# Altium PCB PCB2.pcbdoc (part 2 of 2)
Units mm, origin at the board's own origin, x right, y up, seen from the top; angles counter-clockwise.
Board outline 189.74 x 136.02 mm, 2 copper layers (Top Layer, Bottom Layer); 111 components, 66 nets, 434 pads, 460 vias.
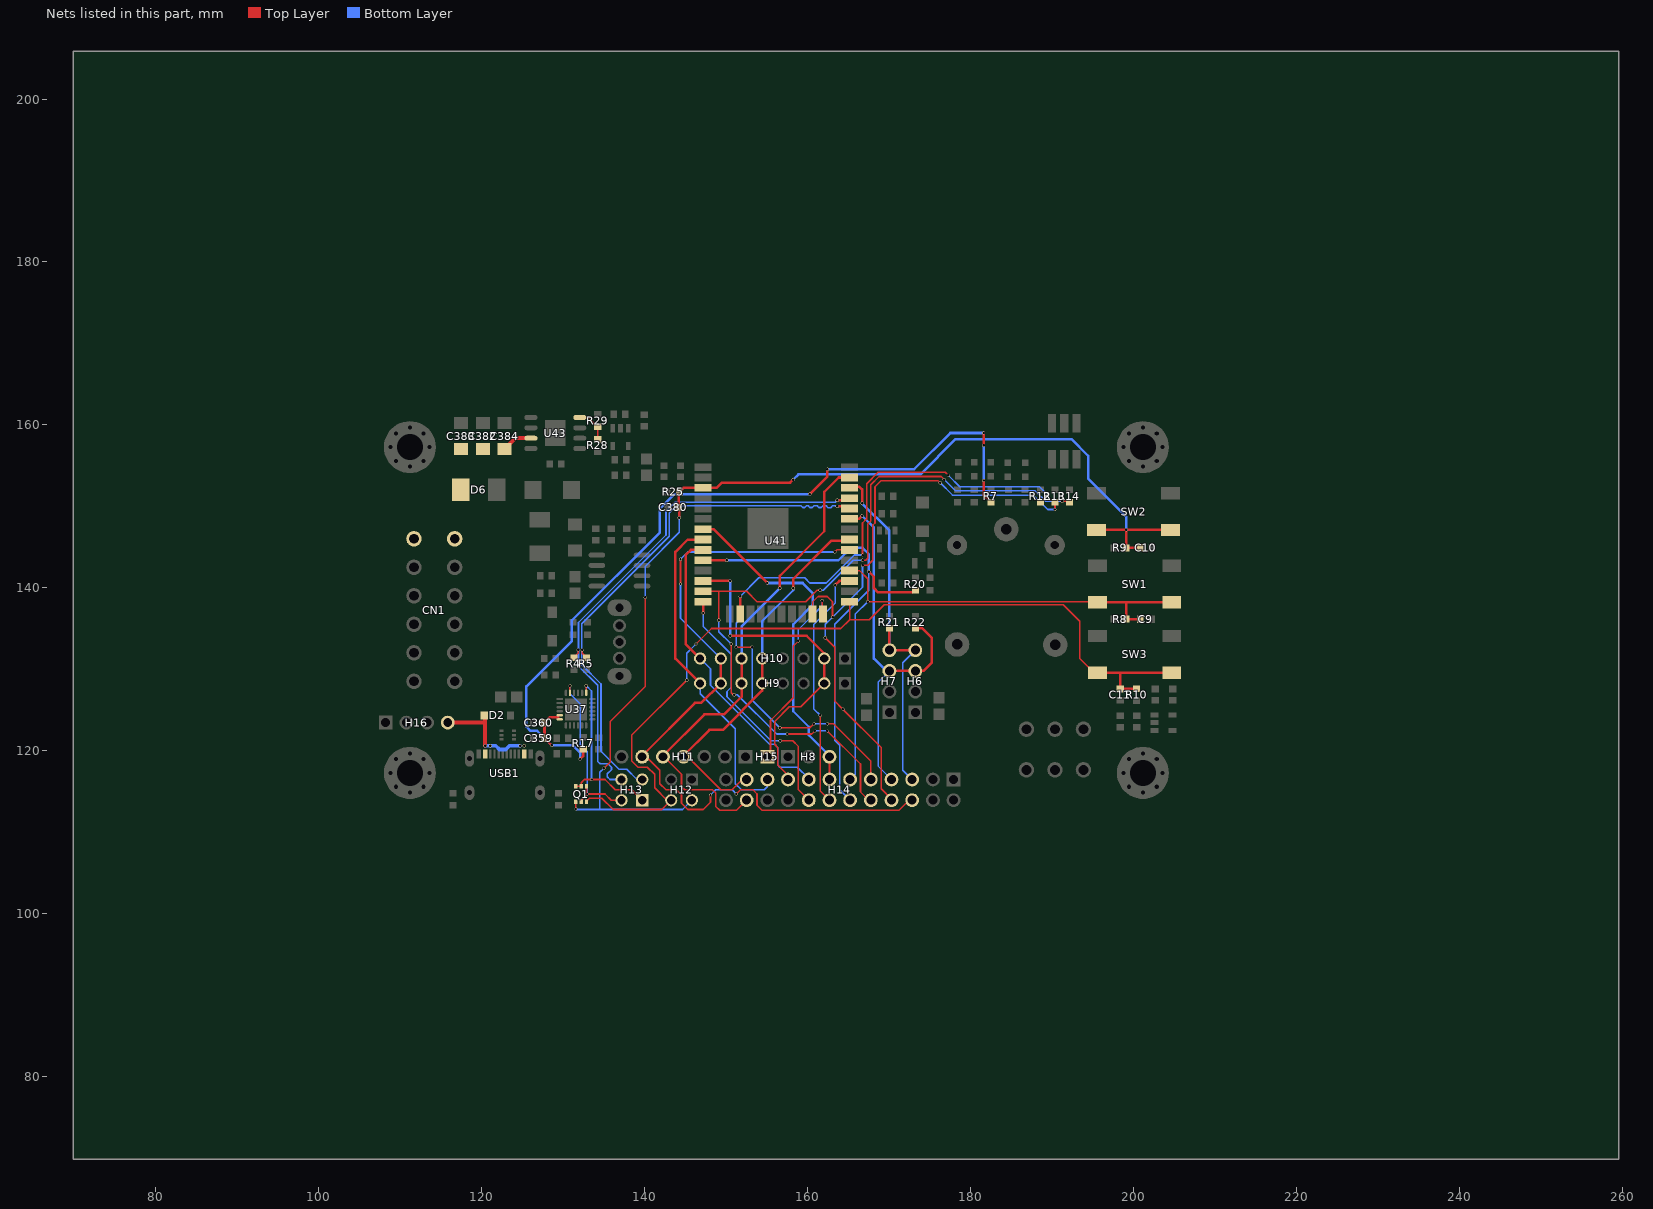
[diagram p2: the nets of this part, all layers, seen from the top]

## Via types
v1: diameter 0.4, hole 0.3, Top Layer to Bottom Layer, 460 vias

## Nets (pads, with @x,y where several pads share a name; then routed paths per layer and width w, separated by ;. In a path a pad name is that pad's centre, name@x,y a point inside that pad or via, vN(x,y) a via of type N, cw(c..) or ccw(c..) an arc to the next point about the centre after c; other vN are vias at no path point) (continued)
DTR: H13.2 Q1.1 Q1.5 U37.23 | length 21.9
  Top Layer w0.2: U37.23@130.822,127.095 v1(130.822,127.984) ; Q1.5@132.207,113.731 132.207,113.919 v1(132.969,114.681) ; Q1.1@132.857,115.631 132.857,114.681 v1(132.969,114.681) ; H13.2@137.16,113.919 135.89,113.919 135.128,114.681 v1(132.969,114.681)
  Bottom Layer w0.2: v1(130.822,127.984) 130.822,126.988 132.08,125.73 132.08,120.777 132.969,119.888 v1(132.969,114.681)
EN: C10.1 C380.1 H12.2 Q1.4 R9.1 R25.2 SW2.3 SW2.4 U41.3 | length 136.5
  Top Layer w0.2: v1(131.557,112.842) Q1.4@131.557,113.731 ; v1(135.001,117.856) 135.763,118.618 135.763,123.571 140.081,127.889 v1(140.081,138.811)
  Top Layer w0.312: v1(144.261,148.59) 144.261,149.809 C380.1@144.21,149.86 144.21,151.712 R25.2@144.263,151.765 144.769,152.271 U41.3@147.172,152.271 148.842,152.271 149.479,152.908 157.863,152.908 v1(158.242,153.287) ; SW2.3@195.475,147.102 v1(199.154,147.102) ; C10.1@200.849,144.907 R9.1@199.127,144.907 199.154,144.933 v1(199.154,147.102) ; SW2.4@204.575,147.102 v1(199.154,147.102)
  Bottom Layer w0.2: v1(131.557,112.842) 131.623,112.776 134.479,112.776 ; v1(135.001,117.856) 134.479,117.334 134.479,112.776 ; v1(140.081,138.811) 140.081,142.621 144.261,146.801 v1(144.261,148.59) ; H12.2@145.796,113.919 144.653,112.776 134.479,112.776
  Bottom Layer w0.312: v1(158.242,153.287) 158.879,153.924 173.863,153.924 178.181,158.242 192.405,158.242 194.437,156.21 194.437,153.416 199.136,148.717 v1@199.136,147.066
FB: R28.1 R29.1 U43.4 | length 4.2
  Top Layer w0.2: U43.4@132.032,160.909 133.096,160.909 134.23,159.775 R29.1@134.239,159.775 R28.1@134.239,158.233
GND: 
IO0: C11.1 H12.4 Q1.6 R10.1 SW3.3 SW3.4 U41.25 | length 109.9
  Top Layer w0.2: Q1.6@132.857,113.731 132.857,113.807 133.223,114.173 134.747,114.173 136.144,112.776 142.113,112.776 H12.4@143.256,113.919 142.748,113.919 141.224,115.443 141.224,117.094 140.335,117.983 139.192,117.983 138.43,118.745 138.43,121.92 v1(145.161,128.651) ; v1(146.304,133.096) 148.209,135.001 164.084,135.001 165.172,136.089 ; U41.25@165.172,138.301 165.172,136.089 ; SW3.3@195.602,129.576 195.163,129.576 193.421,131.318 193.421,135.89 191.389,137.922 169.418,137.922 167.585,136.089 165.172,136.089
  Top Layer w0.312: SW3.3@195.602,129.576 198.422,129.576 ; R10.1@200.406,127.626 198.427,127.626 C11.1@198.374,127.573 198.374,129.528 198.422,129.576 ; SW3.4@204.702,129.576 198.422,129.576
  Bottom Layer w0.2: v1(145.161,128.651) 145.161,131.953 v1(146.304,133.096)
IO2: H15.1 U41.24 | length 23.7
  Top Layer w0.2: H15.1@155.067,119.253 155.448,119.634 155.448,123.698 158.242,126.492 158.242,132.842 v1(158.877,133.477) ; v1(161.798,138.43) 161.798,136.87 U41.24@161.887,136.781
  Bottom Layer w0.2: v1(158.877,133.477) 158.877,134.874 161.798,137.795 v1(161.798,138.43)
IO12: H14.16 U41.14 | length 31.7
  Top Layer w0.2: v1(156.654,121.221) 158.178,121.221 158.877,120.523 158.877,115.189 H14.16@160.147,113.919
  Top Layer w0.312: U41.14@147.172,138.301 147.193,138.28 v1(147.193,136.906)
  Bottom Layer w0.2: v1(147.193,136.906) 147.193,135.255 150.622,131.826 150.622,127.762 150.114,127.254 150.114,126.619 155.511,121.221 v1(156.654,121.221)
IO16: H14.14 U41.27 | length 30.3
  Top Layer w0.2: v1(161.544,124.333) 161.544,115.062 H14.14@162.687,113.919
  Top Layer w0.312: v1(163.394,140.333) 163.902,140.841 U41.27@165.172,140.841
  Bottom Layer w0.2: v1(161.544,124.333) 160.782,125.095 160.782,135.509 163.394,138.121 v1(163.394,140.333)
IO35: H8.3 H14.13 U41.7 | length 42.4
  Top Layer w0.2: H14.13@162.687,116.459 H8.3@162.687,119.38
  Top Layer w0.312: U41.7@147.172,147.191 148.465,147.191 v1(155.067,140.589)
  Bottom Layer w0.312: v1(155.067,140.589) 159.385,140.589 160.655,139.319 160.655,137.922 158.242,135.509 158.242,124.841 160.147,122.936 160.147,121.92 H8.3@162.687,119.38
LED_B: H14.10 R14.1 U41.13 | length 96.3
  Top Layer w0.2: U41.13@147.172,139.571 149.098,139.571 ; v1(149.098,136.017) 149.098,139.571 ; v1(150.622,133.096) 150.622,127.127 150.876,126.873 v1(151.003,126.873) ; v1(157.48,122.047) 160.528,122.047 v1(160.909,122.428) ; v1(161.544,139.698) 161.161,139.698 159.766,138.303 153.797,138.303 152.529,139.571 149.098,139.571 ; v1(162.433,122.428) 166.497,118.364 166.497,114.935 167.513,113.919 H14.10@167.767,113.919 ; v1(166.751,143.383) 167.132,143.383 167.386,143.637 167.386,147.828 167.767,148.209 167.767,152.654 168.783,153.67 176.403,153.67 v1(176.784,153.289) ; v1(191.262,150.631) 192.024,150.631 R14.1@192.151,150.504
  Bottom Layer w0.2: v1(149.098,136.017) 149.098,134.62 v1(150.622,133.096) ; v1(151.003,126.873) 151.384,126.873 156.21,122.047 v1(157.48,122.047) ; v1(160.909,122.428) v1(162.433,122.428) ; v1(161.544,139.698) 161.923,139.698 165.608,143.383 v1(166.751,143.383) ; v1(176.784,153.289) 178.181,151.892 187.96,151.892 189.23,150.622 v1@191.262,150.622
LED_G: H14.8 R13.1 U41.23 | length 75.9
  Top Layer w0.2: U41.23@160.617,136.781 160.617,138.265 161.29,138.938 162.433,138.938 163.068,138.303 v1(163.068,136.398) ; v1(162.179,133.858) 163.322,132.715 163.322,126.111 v1(164.338,125.095) 169.037,120.396 169.037,115.316 170.307,114.046 H14.8@170.307,113.919 ; v1(166.751,142.748) 167.386,142.748 168.021,143.383 168.021,147.701 168.275,147.955 168.275,152.4 169.037,153.162 176.022,153.162 v1(176.276,152.908) ; v1(190.373,149.615) R13.1@190.373,150.504
  Bottom Layer w0.2: v1(162.179,133.858) 162.179,135.509 v1(163.068,136.398) 166.751,140.081 v1(166.751,142.748) ; v1(176.276,152.908) 177.8,151.384 187.706,151.384 189.475,149.615 v1(190.373,149.615)
LED_R: H14.9 R12.1 U41.16 | length 89.2
  Top Layer w0.2: v1(151.257,132.715) v1(153.191,132.715) ; v1(156.591,122.809) 160.274,122.809 v1(160.782,123.317) ; v1(162.433,123.317) 163.195,123.317 167.767,118.745 H14.9@167.767,116.459 ; v1(166.751,144.018) 166.751,147.955 167.259,148.463 167.259,152.781 168.656,154.178 176.911,154.178 v1(177.292,153.797) ; R12.1@188.595,150.504 v1(189.484,151.393)
  Top Layer w0.312: U41.16@151.727,136.781 v1(151.727,138.94)
  Bottom Layer w0.2: v1(151.257,132.715) 151.257,135.636 151.727,136.106 v1(151.727,138.94) 154.011,141.224 159.639,141.224 160.274,140.589 162.306,140.589 165.735,144.018 v1(166.751,144.018) ; v1(153.191,132.715) 153.191,126.209 v1(156.591,122.809) ; v1(160.782,123.317) v1(162.433,123.317) ; v1(177.292,153.797) 178.689,152.4 188.477,152.4 v1(189.484,151.393)
MISO: H9.5 H10.5 H11.4 H14.21 U41.31 | length 46.6
  Top Layer w0.2: H11.4@144.78,119.38 145.161,119.38 149.352,115.189 150.726,115.189 151.996,116.459 H14.21@152.527,116.459
  Top Layer w0.312: H11.4@144.78,119.38 147.955,122.555 149.596,122.555 154.432,127.391 H9.5@154.432,128.27 H10.5@154.432,131.318 ; v1(158.242,139.954) 158.242,141.097 162.941,145.796 165.047,145.796 U41.31@165.172,145.921
  Bottom Layer w0.312: H10.5@154.432,131.953 154.432,135.89 158.242,139.7 v1(158.242,139.954)
MOSI: H9.6 H10.6 H11.5 H14.22 U41.37 | length 60.7
  Top Layer w0.2: H11.5@142.24,119.38 144.526,117.094 144.526,115.57 144.907,115.189 148.336,115.189 148.717,114.808 148.717,113.157 149.206,112.668 151.276,112.668 H14.22@152.527,113.919
  Top Layer w0.312: H11.5@142.24,119.38 147.32,124.46 149.733,124.46 151.892,126.619 H9.6@151.892,128.27 H10.6@151.892,131.318 ; v1(156.591,139.954) 156.591,141.478 162.052,146.939 162.052,151.765 163.83,153.543 165.17,153.543 U41.37@165.172,153.541
  Bottom Layer w0.312: H10.6@151.892,131.953 151.892,135.255 v1(156.591,139.954)
RELAY: H14.12 R20.1 U41.10 | length 61.7
  Top Layer w0.312: U41.10@147.172,143.381 v1(150.093,143.381) ; v1(167.515,141.986) 168.148,141.353 168.148,139.954 168.656,139.446 172.847,139.446 173.11,139.709 R20.1@173.228,139.709
  Bottom Layer w0.2: H14.12@165.227,113.919 163.957,115.189 163.957,120.65 163.322,121.285 163.322,135.509 167.515,139.702 v1(167.515,141.986)
  Bottom Layer w0.312: v1(150.093,143.381) 163.785,143.381 165.311,144.907 166.751,144.907 167.515,144.143 v1(167.515,141.986)
RFID0_SS: H9.8 H14.19 U41.8 | length 40.6
  Top Layer w0.312: H9.8@146.431,128.651 143.764,131.318 143.764,144.399 145.286,145.921 U41.8@147.172,145.921 ; H9.8@146.558,128.778 H9.8@146.812,128.778
  Bottom Layer w0.2: H9.8@146.812,128.27 146.812,127 151.13,122.682 151.13,115.951 151.892,115.189 154.686,115.189 155.067,115.57 H14.19@155.067,116.459
RFID1_SS: H10.8 H14.15 U41.9 | length 37.9
  Top Layer w0.312: H10.8@146.812,131.318 145.034,133.096 145.034,144.018 145.667,144.651 U41.9@147.172,144.651
  Bottom Layer w0.2: H10.8@146.812,131.318 148.082,130.048 148.082,128.016 155.321,120.777 155.956,120.777 156.337,120.396 156.337,118.237 156.591,117.983 158.75,117.983 160.147,116.586 H14.15@160.147,116.459
RFID_RST: H9.2 H10.2 H14.17 U41.12 | length 41.4
  Top Layer w0.2: H14.17@157.607,116.459 157.607,116.967 156.337,118.237 156.337,120.396 155.956,120.777 155.956,123.571 157.761,125.376 159.158,125.376 H9.2@162.052,128.27
  Top Layer w0.312: U41.12@147.172,140.841 v1(150.497,140.841) ; v1(150.495,134.112) 159.893,134.112 H10.2@162.052,131.953 ; H9.2@162.052,128.27 H10.2@162.052,131.318
  Bottom Layer w0.312: v1(150.495,134.112) 150.497,134.114 v1(150.497,140.841)
RTS: H13.1 Q1.2 Q1.3 U37.19 | length 22.5
  Top Layer w0.2: Q1.3@131.557,115.631 Q1.2@132.207,115.631 132.207,116.078 132.588,116.459 v1(133.477,116.459) 135.128,116.459 136.398,115.189 138.43,115.189 H13.1@139.7,113.919 ; U37.19@132.822,127.095 v1(132.822,127.984)
  Bottom Layer w0.2: v1(132.822,127.984) 133.477,127.329 v1(133.477,116.459)
RX: H13.4 R4.2 U41.35 | length 65.8
  Top Layer w0.2: R4.2@131.318,131.436 131.826,131.944 v1(131.826,132.367)
  Top Layer w0.312: v1(163.648,150.747) 164.706,150.747 164.96,151.001 U41.35@165.172,151.001
  Bottom Layer w0.2: H13.4@137.16,116.459 135.737,116.459 135.409,116.787 135.409,117.159 135.92,117.67 135.92,117.953 135.493,118.38 134.534,118.38 134.239,118.675 134.239,128.016 131.88,130.375 131.88,132.313 v1(131.826,132.367) 131.88,132.421 131.88,135.748 142.621,146.489 142.621,149.352 143.764,150.495 163.396,150.495 v1(163.648,150.747)
SCK: H9.7 H10.7 H11.6 H14.6 U41.30 | length 93.6
  Top Layer w0.2: H11.6@139.7,119.253 140.208,119.253 141.859,117.602 141.859,115.951 142.621,115.189 143.891,115.189 144.526,114.554 144.526,113.538 145.288,112.776 147.193,112.776 148.082,113.665 v1(148.082,114.554) ; v1(144.399,140.462) v1(144.399,143.51) ; v1(151.257,114.681) 151.765,115.189 153.289,115.189 153.797,114.681 153.797,113.284 154.413,112.668 171.215,112.668 172.466,113.919 H14.6@172.847,113.919 ; v1(163.322,144.399) 163.574,144.651 U41.30@165.172,144.651
  Top Layer w0.312: H11.6@139.7,119.38 146.177,125.857 146.939,125.857 H9.7@149.352,128.27 H10.7@149.352,131.318
  Bottom Layer w0.2: v1(144.399,140.462) 144.399,136.271 H10.7@149.352,131.318 ; v1(144.399,143.51) 145.288,144.399 v1(163.322,144.399) ; v1(148.082,114.554) 148.717,115.189 150.749,115.189 v1(151.257,114.681)
SCL: H6.4 H7.4 H14.5 R21.2 U41.36 | length 45.7
  Top Layer w0.312: U41.36@165.172,152.271 165.301,152.4 166.37,152.4 166.696,152.074 v1(166.696,150.366) ; R21.2@170.053,135.01 H7.4@170.053,132.334 H6.4@173.228,132.334
  Bottom Layer w0.2: H14.5@172.847,116.459 171.704,117.602 171.704,130.81 H6.4@173.228,132.334
  Bottom Layer w0.312: v1(166.696,150.366) 170.053,147.009 H7.4@170.053,132.334
SDA: H6.3 H7.3 H14.7 R22.2 U41.33 | length 48.1
  Top Layer w0.312: U41.33@165.172,148.461 166.315,148.461 v1(166.696,148.842) ; H7.3@170.053,129.794 H6.3@173.228,129.794 174.244,129.794 175.26,130.81 175.26,133.858 174.108,135.01 R22.2@173.228,135.01
  Bottom Layer w0.2: H7.3@170.053,129.794 168.656,128.397 168.656,118.11 H14.7@170.307,116.459
  Bottom Layer w0.312: v1(166.696,148.842) 168.148,147.39 168.148,131.318 169.672,129.794 H7.3@170.053,129.794
SW: C9.1 H14.11 R8.1 SW1.3 SW1.4 U41.28 | length 69.3
  Top Layer w0.2: U41.28@165.172,142.111 166.372,142.111 167.386,141.097 v1(167.386,138.303) 195.511,138.303 SW1.3@195.602,138.212
  Top Layer w0.312: SW1.3@195.602,138.212 199.111,138.212 ; C9.1@200.849,136.144 R8.1@199.127,136.144 199.127,138.196 199.111,138.212 ; SW1.4@204.702,138.212 199.111,138.212
  Bottom Layer w0.2: H14.11@165.227,116.459 165.862,117.094 165.862,136.779 v1(167.386,138.303)
TX: H13.3 R5.2 U41.34 | length 65.8
  Top Layer w0.2: v1(132.334,132.367) 132.334,131.944 R5.2@132.842,131.436
  Top Layer w0.312: v1(163.648,149.985) 164.706,149.985 164.96,149.731 U41.34@165.172,149.731
  Bottom Layer w0.2: H13.3@139.7,116.459 139.065,116.459 137.795,117.729 136.837,117.729 134.639,119.927 134.639,128.182 132.28,130.541 132.28,132.313 v1(132.334,132.367) 132.28,132.421 132.28,135.582 143.021,146.323 143.021,149.186 143.93,150.095 159.169,150.095 159.413,149.852 159.672,149.852 159.88,150.06 160.073,150.06 160.273,149.86 160.578,149.86 160.778,150.06 161.172,150.06 161.372,149.86 161.69,149.86 161.902,150.072 162.281,150.072 162.512,149.841 162.85,149.841 163.104,150.095 163.538,150.095 v1(163.648,149.985)
USB5V: D2.1 H16.4 USB1.2 USB1.11 | length 13
  Top Layer w0.5: H16.4@115.824,123.444 120.387,123.444 120.409,123.466 ; D2.1@120.31,124.333 120.409,124.234 120.409,123.466 ; v1(120.409,120.612) 120.409,123.466
  Bottom Layer w0.44: v1(120.409,120.612) v1(121.044,120.612) 121.704,120.612 122.174,120.142 122.936,120.142 123.406,120.612 v1(124.701,120.612)
  other v1: 125.209,120.612
VCC: C382.2 C383.2 C384.2 CN1.1 D6.2 U43.7 | length 3.8
  Top Layer w0.5: C384.2@122.809,157.03 124.148,158.369 U43.7@126.032,158.369
VDD: C359.2 C360.2 R7.1 R17.1 U37.5 U37.6 | length 101.8
  Top Layer w0.312: v1(128.589,120.65) C359.2@127.7,121.539 C360.2@127.7,123.444 128.335,124.079 129.413,124.079 ; v1(132.08,118.966) 132.461,119.347 R17.1@132.461,120.151 ; v1(160.274,151.511) 162.433,153.67 v1(162.433,154.559) ; v1(181.61,153.171) 181.61,151.393 R7.1@182.499,150.504 ; v1(181.61,157.48) v1(181.61,159.004)
  Bottom Layer w0.312: v1(132.08,118.966) 132.08,119.761 131.191,120.65 v1(128.589,120.65) 126.811,122.428 125.984,122.428 125.476,122.936 125.476,127.889 131.064,133.477 131.064,136.017 141.859,146.812 141.859,149.733 143.637,151.511 v1(160.274,151.511) ; v1(162.433,154.559) 173.101,154.559 177.546,159.004 v1(181.61,159.004) ; v1(181.61,153.171) v1(181.61,157.48)
pads on no net: C1.2 C2.2 C3.2 C6.1 C9.2 C10.2 C11.2 C351.1 C352.1 C353.1 C354.1 C355.1 C356.1 C357.1 C358.1 C359.1 C360.1 C361.1 C362.1 C363.2 C364.2 C369.1 C370.1 C371.1 C372.1 C373.1 C374.1 C375.1 C376.1 C377.2 C378.2 C379.2 C380.2 C382.1 C383.1 C384.1 C385.1 C386.1 C387.1 C388.1 CN1.2 D1.2 D5.2 D6.1 H1.1 H2.1 H3.1 H4.1 H6.1 H7.1 H8.1 H9.3 H9.4 H10.3 H10.4 H11.2 H12.3 H14.3 H14.4 H16.1 LED白.1 LED红.2 LED绿.1 LED蓝.2 Q2.2 R1.2 R2.2 R15.2 R19.2 R29.2 SW1.1 SW1.2 SW2.1 SW2.2 SW3.1 SW3.2 U31.2 U31.4 U34.2 U36.3 U36.4 U36.5 U37.1 U37.2 U37.10 U37.11 U37.12 U37.13 U37.14 U37.15 U37.17 U37.18 U37.22 U37.24 U37.25 U40.2 U40.4 U41.1 U41.4 U41.5 U41.15 U41.17 U41.18 U41.19 U41.20 U41.21 U41.22 U41.32 U41.38 U41.39 U42.2 U42.4 U43.2 U43.3 U43.5 U43.6 U43.9 USB1.1 USB1.3 USB1.9 USB1.12 USB1.13 USB1.14
copper on no net: | length 8.8
  Top Layer w0.2: v1(122.936,123.19) 124.079,123.19 124.46,123.571 124.46,124.714 126.111,126.365 128.29,126.365 v1(128.81,125.845) 129.572,125.845
  other v1: 125.603,113.157 169.037,113.157 156.337,113.284 133.731,113.538 141.351,113.792 138.43,113.919 122.047,114.681 160.782,115.189 167.138,115.189 168.408,115.189 133.731,115.316 135.161,115.367 138.43,115.881 147.066,116.078 123.388,116.134 136.017,116.967 116.078,117.094 129.921,117.094 149.097,117.475 151.638,117.475 147.828,117.729 155.956,117.729 131.572,117.856 145.542,117.856 160.782,117.856 162.052,117.856 167.132,118.364 169.926,118.745 178.306,118.745 164.846,118.872 134.874,118.999 107.569,120.396 163.12,120.63 174.752,120.65 153.67,120.777 204.47,120.777 122.428,120.904 159.893,120.904 114.681,121.031 142.621,121.031 119.126,121.158 145.288,121.158 162.306,121.158 167.005,121.158 136.398,121.793 121.031,121.92 170.942,121.92 140.589,122.047 172.974,122.047 112.014,122.174 150.495,122.301 178.181,122.428 118.364,122.682 146.812,122.682 154.813,122.682 164.846,122.809 129.295,122.878 141.478,122.936 144.706,123.13 157.226,123.444 203.791,123.507 139.202,123.825 142.299,123.831 130.556,124.067 132.588,124.067 160.655,124.079 114.554,124.206 127,124.281 162.596,124.289 121.92,124.333 137.922,124.587 152.908,124.587 135.509,124.841 140.462,124.968 131.572,125.083 146.685,125.095 194.691,125.095 118.11,125.603 144.526,125.603 113.665,125.73 130.556,126.099 132.588,126.099 119.38,126.238 156.718,126.492 161.798,126.492 162.596,126.492 159.258,126.746 135.89,126.873 140.335,127.127 128.651,127.254 137.668,127.254 195.961,127.254 143.129,127.762 194.183,128.016 129.921,128.143 125.603,129.286 141.478,129.413 175.768,129.54 146.939,129.667 122.428,129.794 149.987,129.794 151.226,129.794 152.542,129.794 153.797,129.794 155.067,129.794 157.099,129.794 159.512,129.794 161.29,129.921 167.005,129.921 114.3,130.048 130.302,130.048 134.606,130.063 199.263,130.556 108.585,130.683 126.365,130.683 174.498,131.175 134.606,131.624 195.081,131.826 120.65,131.953 167.005,131.99 204.216,132.08 144.526,132.207 198.755,132.207 141.859,132.588 162.306,132.842 159.639,132.969 155.035,133.096 157.099,133.096 164.465,133.096 174.498,133.322 152.781,133.477 114.046,133.731 115.65,133.731 130.048,133.731 145.669,133.731 168.91,133.985 171.678,133.985 161.417,134.112 125.603,134.177 135.001,134.366 164.846,134.366 167.132,135.001 143.129,135.128 123.698,135.382 141.859,135.484 134.239,135.763 204.47,135.763 175.133,136.017 169.037,136.652 126.492,136.779 146.177,136.779 179.578,136.779 188.849,136.779 167.259,136.906 148.209,137.033 119.256,137.208 114.554,137.414 143.129,138.227 152.529,138.383 154.178,138.811 129.921,138.938 136.906,139.231 125.349,139.319 176.945,139.7 179.324,139.7 199.136,139.954 141.859,140.021 129.921,140.28 204.702,140.462 151.511,140.589 143.129,140.908 188.341,140.97 192.676,140.97 108.795,141.097 114.574,141.097 119.507,141.097 162.179,141.224 169.037,141.732 177.292,142.113 200.152,142.22 171.958,142.748 156.122,142.823 151.003,142.875 178.816,143.002 129.54,143.256 141.859,143.255 143.129,143.467 135.89,143.758 168.91,143.764 124.527,143.997 152.996,145.109 155.155,145.109 157.314,145.109 149.098,145.161 161.163,145.161 193.548,145.161 121.92,145.288 145.542,145.288 108.331,145.415 129.168,145.492 172.339,145.551 144.145,145.796 145.288,146.812 163.195,146.913 124.968,146.939 160.02,147.066 152.996,147.268 155.155,147.268 157.314,147.268 188.341,147.447 129.727,147.601 177.927,147.701 143.637,147.828 169.799,148.046 159.258,148.336 200.406,148.336 137.668,148.59 149.86,148.59 163.195,148.59 180.782,148.593 122.555,148.844 135.001,148.971 176.911,148.971 193.548,148.998 108.839,149.225 145.542,149.352 203.79,149.352 152.996,149.427 155.155,149.427 157.314,149.427 172.339,149.479 112.649,149.733 132.08,149.733 169.037,150.108 169.799,150.108 199.238,150.647 136.906,150.876 141.986,151.003 149.524,151.003 157.353,151.003 161.29,151.257 163.322,151.511 134.239,151.59 176.276,151.638 113.919,152.019 124.333,152.138 173.99,152.146 201.425,152.524 193.548,152.78 108.458,152.908 148.971,153.289 128.143,153.67 196.342,153.67 145.542,154.305 115.316,154.432 149.352,154.559 153.072,154.559 155.702,154.559 159.081,154.559 177.722,154.546 188.849,154.566 120.65,154.686 133.096,154.813 135.128,155.067 124.333,155.575 168.402,156.464 128.044,156.504 180.848,156.591 130.683,156.718 137.096,157.284 188.849,157.353 180.086,157.48 128.143,157.734 129.921,157.734 194.437,157.861 171.45,158.242 118.497,158.623 121.302,158.623 129.032,159.004 133.223,159.131 142.186,159.229 138.868,159.448 170.307,159.639 144.272,159.766 128.143,160.274 129.921,160.274 196.342,160.274 143.002,160.782 114.046,160.909 175.766,161.036 181.362,161.036 184.785,161.036 129.413,161.417 188.722,161.417 124.587,161.544

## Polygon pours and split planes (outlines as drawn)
USB5V on Top Layer (solid, remove dead copper): 120.09,119.026 120.704,119.026 120.704,121.02 120.09,121.02
USB5V on Bottom Layer (solid, remove dead copper, pour order 64): 120.015,120.269 121.412,120.269 121.412,121.031 120.015,121.031
USB5V on Top Layer (solid, remove dead copper, pour order 2): 120.09,120.339 121.324,120.339 121.324,121.031 120.09,121.031
+5V on Bottom Layer (solid, remove dead copper, pour order 66): 127.725,134.338 129.527,134.338 129.527,135.514 127.725,135.514
USB5V on Top Layer (solid, remove dead copper, pour order 4): 124.405,120.343 125.511,120.343 125.511,120.933 124.405,120.933
$1N9535 on Bottom Layer (solid, remove dead copper, pour order 68): 188.595,116.078 192.024,116.078 192.024,126.873 188.595,126.873
VDD on Top Layer (solid, remove dead copper, pour order 6): 129.032,123.571 130.048,123.571 130.048,124.587 129.032,124.587
$1N9535 on Bottom Layer (solid, remove dead copper, pour order 70): 182.245,126.131 186.69,126.131 186.69,149.479 182.245,149.479
$1N9535 on Bottom Layer (solid, remove dead copper, pour order 72): 182.245,125.73 192.024,125.73 192.024,130.048 182.245,130.048
+5V on Top Layer (solid, remove dead copper, pour order 8): 130.048,122.555 131.064,122.555 131.064,123.571 130.048,123.571
VCC on Top Layer (solid, remove dead copper, pour order 10): 110.109,144.653 118.491,144.653 118.491,147.574 110.109,147.574
3V3 on Bottom Layer (solid, remove dead copper, pour order 74): 200.877,125.483 202.292,125.483 202.292,126.873 200.877,126.873
VCC on Top Layer (solid, remove dead copper, pour order 12): 116.332,146.812 118.491,146.812 118.491,153.416 116.332,153.416
$1N9531 on Bottom Layer (solid, remove dead copper, pour order 76): 184.785,116.078 188.214,116.078 188.214,124.206 184.785,124.206
$1N9540 on Bottom Layer (solid, remove dead copper, pour order 78): 192.405,116.078 195.326,116.078 195.326,124.206 192.405,124.206
VCC on Top Layer (solid, remove dead copper, pour order 14): 116.332,153.416 118.453,153.416 118.453,157.773 116.332,157.773
3.3_SENSOR on Bottom Layer (solid, remove dead copper, pour order 80): 170.97,139.97 171.958,139.97 171.958,141.226 170.97,141.226
VCC on Top Layer (solid, remove dead copper, pour order 16): 116.309,156.059 123.641,156.059 123.641,157.773 116.309,157.773
+5V on Top Layer (solid, remove dead copper, pour order 18): 127.762,133.803 129.493,133.803 129.493,135.509 127.762,135.509
3.3_SENSOR on Bottom Layer (solid, remove dead copper, pour order 82): 171.196,136.017 172.466,136.017 172.466,137.033 171.196,137.033
+5V on Bottom Layer (solid, remove dead copper, pour order 84): 196.977,122.047 197.866,122.047 197.866,124.079 196.977,124.079
3.3_SENSOR on Top Layer (solid, remove dead copper, pour order 20): 168.084,125.666 168.084,127.825 166.56,127.825 166.56,125.666
3V3 on Top Layer (solid, remove dead copper, pour order 22): 135.423,145.067 137.011,145.067 137.011,146.558 135.423,146.558
+5V on Bottom Layer (solid, remove dead copper, pour order 86): 124.587,121.539 125.755,121.539 125.755,122.682 124.587,122.682
$1N9540 on Top Layer (solid, remove dead copper, pour order 24): 181.356,112.195 195.23,112.195 195.23,115.697 181.356,115.697
+5V on Bottom Layer (solid, remove dead copper, pour order 88): 138.049,144.526 139.192,144.526 139.192,145.669 138.049,145.669
$1N9540 on Top Layer (solid, remove dead copper, pour order 26): 176.403,130.302 183.388,130.302 183.388,135.636 176.403,135.636
$1N9540 on Top Layer (solid, remove dead copper, pour order 28): 179.959,110.149 184.404,110.149 184.404,135.636 179.959,135.636
3V3 on Bottom Layer (solid, remove dead copper, pour order 90): 136.105,145.034 137.287,145.034 137.287,146.558 136.105,146.558
$1N9540 on Top Layer (solid, remove dead copper, pour order 30): 192.405,115.235 195.23,115.235 195.23,124.206 192.405,124.206
3V3 on Bottom Layer (solid, remove dead copper, pour order 92): 139.065,157.226 139.954,157.226 139.954,158.75 139.065,158.75
$1N9535 on Top Layer (solid, remove dead copper, pour order 32): 188.595,116.078 192.024,116.078 192.024,124.206 188.595,124.206
3V3 on Bottom Layer (solid, remove dead copper, pour order 94): 142.24,157.226 143.002,157.226 143.002,158.623 142.24,158.623
$1N9531 on Top Layer (solid, remove dead copper, pour order 34): 184.785,116.078 188.214,116.078 188.214,124.714 184.785,124.714
3V3 on Bottom Layer (solid, remove dead copper, pour order 96): 186.944,159.512 187.96,159.512 187.96,161.163 186.944,161.163
3V3 on Bottom Layer (solid, remove dead copper, pour order 98): 193.802,159.778 194.552,159.778 194.552,161.163 193.802,161.163
$1N9531 on Top Layer (solid, remove dead copper, pour order 36): 184.785,123.698 188.214,123.698 188.214,135.636 184.785,135.636
$1N9531 on Top Layer (solid, remove dead copper, pour order 38): 184.785,130.683 192.278,130.683 192.278,135.636 184.785,135.636
3V3 on Top Layer (solid, remove dead copper, pour order 40): 200.877,125.483 202.292,125.483 202.292,126.873 200.877,126.873
3.3_SENSOR on Top Layer (solid, remove dead copper, pour order 42): 170.053,139.954 171.958,139.954 171.958,141.226 170.053,141.226
3.3_SENSOR on Top Layer (solid, remove dead copper, pour order 44): 171.196,136.017 172.466,136.017 172.466,137.033 171.196,137.033
3V3 on Top Layer (solid, remove dead copper, pour order 46): 139.065,157.226 139.954,157.226 139.954,158.75 139.065,158.75
3V3 on Top Layer (solid, remove dead copper, pour order 48): 142.24,157.226 143.002,157.226 143.002,158.623 142.24,158.623
3V3 on Top Layer (solid, remove dead copper, pour order 50): 186.944,159.512 187.96,159.512 187.96,161.163 186.944,161.163
3V3 on Top Layer (solid, remove dead copper, pour order 52): 193.802,159.778 194.552,159.778 194.552,161.163 193.802,161.163
+5V on Bottom Layer (solid, remove dead copper, pour order 100): 171.704,151.511 173.101,151.511 173.101,152.908 171.704,152.908
+5V on Top Layer (solid, remove dead copper, pour order 54): 171.704,151.003 173.101,151.003 173.101,152.908 171.704,152.908
USB5V on Top Layer (solid, remove dead copper, pour order 56): 119.761,123.19 120.777,123.19 120.777,124.841 119.761,124.841
USB5V on Top Layer (solid, remove dead copper, pour order 58): 124.405,120.269 125.603,120.269 125.603,120.933 124.405,120.933
USB5V on Top Layer (solid, remove dead copper, pour order 60): 124.909,119.025 125.511,119.025 125.511,120.933 124.909,120.933
no net on Top Layer (solid, remove dead copper, pour order 62): 92.964,95.885 229.235,95.885 229.235,179.324 92.964,179.324
no net on Bottom Layer (solid, remove dead copper, pour order 102): 76.2,76.2 253.238,76.2 253.238,199.517 76.2,199.517

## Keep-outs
Board Outline Layer:
  lines w0.254: 106.172,116.268 ccw(c110.172,116.268) 110.172,112.268 202.172,112.268 ccw(c202.172,116.268) 206.172,116.268 206.172,158.268 ccw(c202.172,158.268) 202.172,162.268 110.172,162.268 ccw(c110.172,158.268) 106.172,158.268 106.172,116.268
Multi-Layer:
  region: 144.907,155.746 167.856,155.746 167.856,163.449 144.907,163.449

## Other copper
Top Layer:
  drawing of 446 lines, arcs and shapes, not listed
Bottom Layer:
  drawing of 159 lines, arcs and shapes, not listed

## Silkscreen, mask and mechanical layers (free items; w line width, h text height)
Top Silkscreen Layer:
  drawing of 195 lines, arcs and shapes, not listed
  text "RELA Y\N" at 179.07,156.337 h1.1 r90
  text "POWER" at 181.229,156.337 h1.5 r90
  text "USB" at 183.261,156.337 h1.5 r90
  text "SENSOR" at 185.293,156.21 h1.5 r90
  text "5V>3V3" at 187.452,156.21 h1.5 r90
  text "RGBLED" at 188.849,152.908 h1.5
  text "EN" at 196.215,148.59 h1.5 r90
  text "EN" at 205.359,148.59 h1.5 r90
  text "12V" at 121.158,145.161 h1.5
  text "GND" at 121.285,141.732 h1.5
  text "SW" at 196.342,139.573 h1.5 r90
  text "SW" at 205.613,139.573 h1.5 r90
  text "CAN_H" at 121.158,138.557 h1.5
  text "CAN_L" at 121.158,134.747 h1.5
  text "RFID" at 160.782,133.985 h1
  text "ON" at 139.7,133.731 h1.5
  text "SCL" at 175.006,133.35 h1 r270
  text "SCK" at 148.336,132.969 h1
  text "MOSI" at 150.876,132.969 h1
  text "MISO" at 153.67,132.969 h1
  text "GND" at 158.242,132.969 h1
  text "3V3" at 163.576,132.969 h1
  text "RST" at 160.909,132.842 h1
  text "SCL" at 168.275,131.572 h1 r90
  text "CAN_H" at 121.285,131.318 h1.5
  text "OFF" at 139.7,131.191 h1.5
  text "RFID1" at 142.621,130.81 h1
  text "IO0" at 196.342,130.81 h1.5 r90
  text "IO0" at 205.486,130.81 h1.5 r90
  text "SDA" at 175.006,130.556 h1 r270
  text "SDA" at 168.275,128.778 h1 r90
  text "CAN_L" at 121.285,127.889 h1.5
  text "RFID0" at 142.494,127.762 h1
  text "3V3" at 177.419,125.984 h1
  text "IO2" at 154.559,125.73 h1
  text "GND" at 156.718,125.73 h1
  text "SENSOR" at 159.131,125.73 h1
  text "3V3" at 164.211,125.603 h1
  text "CAN" at 146.939,125.349 h1
  text "SENSOR" at 149.987,125.349 h1
  text "CAN" at 135.89,125.222 h1
  text "3V3" at 159.258,124.714 h1
  text "RF" at 154.686,124.333 h1
  text "RF" at 157.099,124.333 h1
  text "_INT" at 135.636,124.206 h1
  text "MISO" at 144.018,124.079 h1
  text "_CS" at 146.812,124.079 h1
  text "3V3" at 151.892,124.079 h1
  text "SCK" at 138.557,123.952 h1
  text "MOSI" at 141.097,123.952 h1
  text "GND" at 149.479,123.952 h1
  text "IO35" at 161.671,123.825 h1
  text "GND" at 177.419,123.825 h1
  text "GND" at 164.338,123.698 h1
  text "RF1" at 159.258,123.317 h1
  text "ID0" at 154.559,123.19 h1
  text "RST" at 156.845,123.19 h1
  text "RX" at 136.144,122.555 h1
  text "TX" at 138.684,122.555 h1
  text "GND" at 142.24,122.555 h1
  text "3V3" at 144.78,122.555 h1
  text "CAN TX" at 147.32,122.555 h1
  text "MISO" at 151.638,122.555 h1
  text "IO35" at 161.671,122.428 h1
  text "SS" at 159.512,122.301 h1
  text "CAN" at 154.305,121.92 h1
  text "CAN" at 156.718,121.92 h1
  text "LED" at 167.005,121.666 h1
  text "DTR" at 135.763,121.031 h1
  text "RTS" at 138.557,121.031 h1
  text "IO0" at 142.367,121.031 h1
  text "EN" at 145.288,121.031 h1
  text "CAN RX" at 147.32,121.031 h1
  text "MOSI" at 151.638,121.031 h1
  text "GND" at 107.188,120.904 h1
  text "DP" at 110.109,120.904 h1
  text "DN" at 112.649,120.904 h1
  text "5V" at 115.316,120.904 h1
  text "IO12" at 159.258,120.904 h1
  text "IO16" at 161.798,120.904 h1
  text "SW" at 164.592,120.904 h1
  text "SDA" at 169.418,120.904 h1
  text "INT" at 154.559,120.777 h1
  text "CS" at 157.099,120.777 h1
  text "R" at 167.64,120.65 h1
  text "GND" at 174.625,119.38 h1
  text "RE" at 164.719,119.253 h1
  text "LED" at 166.878,119.253 h1
  text "LED" at 169.418,119.253 h1
  text "SCL" at 172.085,119.253 h1
  text "5V" at 177.546,119.253 h1
  text "LAY" at 164.465,118.11 h1
  text "B" at 167.513,118.11 h1
  text "G" at 170.053,118.11 h1
  text "SCK" at 172.085,117.983 h1
  text "GND" at 174.498,117.983 h1
  text "3V3" at 177.165,117.983 h1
